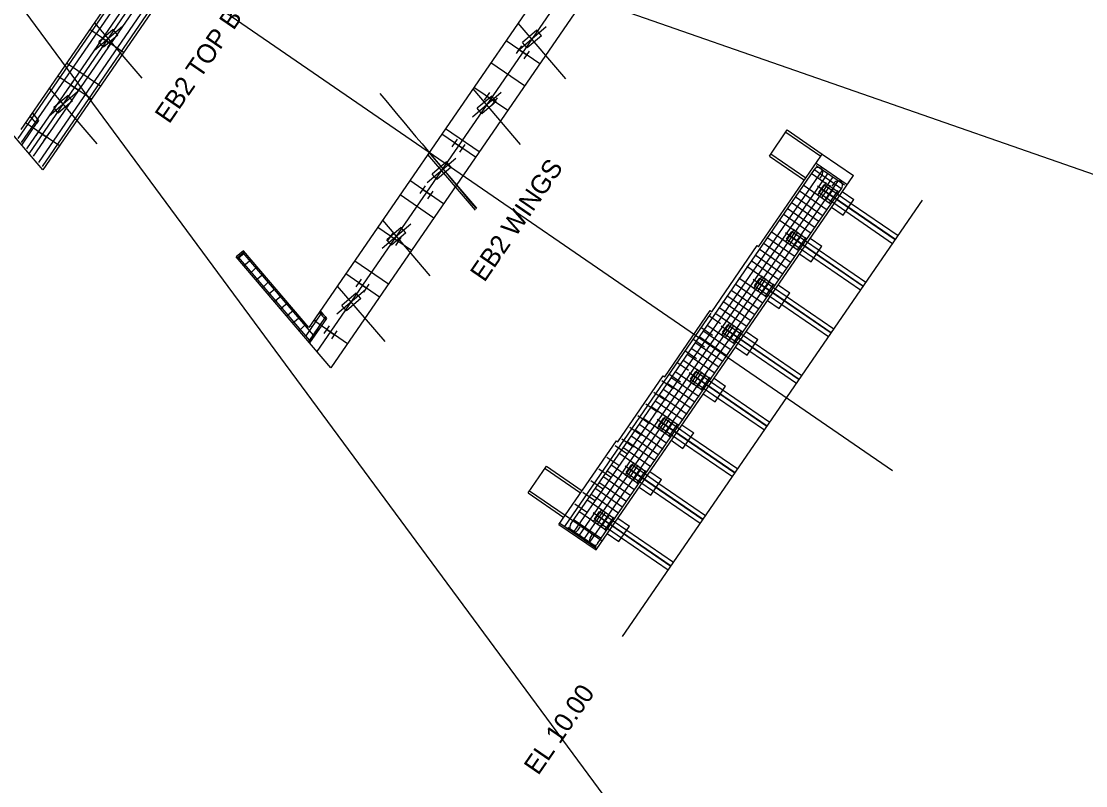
# Model space of a CAD drawing. Extents: x 2378999 to 2381348, y 331302 to 333122.
# Drawn here: x 2379248 to 2379360.9, y 331490.3 to 331571.3 of the extents above; entities that cross this region are included whole.
import ezdxf

# ---------------------------------------------------------------- set-up
doc = ezdxf.new("R2010")
doc.units = 0
for name, color, linetype in [('Arrowhead Terminators', 7, 'Continuous'), ('Dimension Lines', 7, 'Continuous'), ('Dimension Lines CELL', 7, 'Continuous'), ('Mis Work Point CELL', 7, 'Continuous'), ('P_SMU_Bent_Cap', 7, 'Continuous'), ('P_SMU_D_Deck_Outline', 7, 'Continuous'), ('P_SMU_Girder_Concrete', 7, 'Continuous'), ('P_SMU_Mis_L_Lines', 7, 'Continuous'), ('P_SMU_Mis_Long_Chord', 7, 'Continuous'), ('P_SMU_Rebar_B_Bar', 7, 'Continuous'), ('P_SMU_Rebar_H_Bar', 7, 'Continuous'), ('P_SMU_Rebar_K_Bar', 7, 'Continuous'), ('P_SMU_Rebar_U_Bar', 7, 'Continuous'), ('P_SMU_Rebar_V_Bar', 7, 'Continuous'), ('Plan Sheet CELL', 7, 'Continuous'), ('Rebar Lines', 7, 'Continuous'), ('Scratch_Level_0', 7, 'Continuous'), ('Sup Concrete Slab Lines', 7, 'Continuous')]:
    doc.layers.add(name, color=color, linetype=linetype)

msp = doc.modelspace()

# ---------------------------------------------------------------- linework, layer by layer
at = {"layer": 'Arrowhead Terminators'}
for p, q in [((2379247.69, 331558.9), (2379274.11, 331597.35)), ((2379248.06, 331558.46), (2379274.48, 331596.92)), ((2379248.62, 331557.81), (2379275.04, 331596.26)), ((2379275.71, 331595.47), (2379249.3, 331557.02)), ((2379276.27, 331594.82), (2379249.86, 331556.36)), ((2379276.65, 331594.38), (2379250.23, 331555.92)), ((2379306.23, 331517.95), (2379332.11, 331555.6)), ((2379306.57, 331517.12), (2379333, 331555.58)), ((2379307.12, 331516.74), (2379333.55, 331555.2)), ((2379332.91, 331555.05), (2379332.68, 331554.7)), ((2379307.67, 331516.36), (2379334.1, 331554.83)), ((2379308.22, 331515.98), (2379334.65, 331554.45)), ((2379334.18, 331554.17), (2379333.95, 331553.83)), ((2379309.12, 331515.96), (2379334.99, 331553.62)), ((2379305.64, 331517.76), (2379321.16, 331540.36)), ((2379307.04, 331517.39), (2379307.28, 331517.73)), ((2379308.31, 331516.52), (2379308.55, 331516.86))]:
    msp.add_line(p, q, dxfattribs=at)
for centre, start, end in [((2379332.51, 331555.32), 325.5093, 145.5093), ((2379334.59, 331553.9), 325.5093, 145.5093), ((2379306.64, 331517.67), 145.5093, 325.5093), ((2379308.72, 331516.24), 145.5093, 325.5093)]:
    msp.add_arc(centre, 0.49, start, end, dxfattribs=at)
at = {"layer": 'Dimension Lines'}
for p, q in [((2379316.62, 331479.98), (2379154.62, 331699.5)), ((2379368.09, 331552.83), (2379115.15, 331641.03)), ((2379331.75, 331555.23), (2379334.73, 331553.17)), ((2379332.02, 331555.62), (2379335, 331553.57)), ((2379332.29, 331556.01), (2379335.27, 331553.96)), ((2379330.9, 331553.99), (2379333.88, 331551.94)), ((2379332.43, 331552.84), (2379333.37, 331554.21)), ((2379332.84, 331552.55), (2379333.79, 331553.93)), ((2379330.05, 331552.75), (2379333.04, 331550.7)), ((2379330.47, 331553.37), (2379333.46, 331551.32)), ((2379333.25, 331552.27), (2379334.2, 331553.64)), ((2379333.67, 331551.99), (2379334.61, 331553.36)), ((2379329.62, 331552.14), (2379332.61, 331550.08)), ((2379328.77, 331550.9), (2379331.76, 331548.85)), ((2379329.2, 331551.52), (2379332.19, 331549.46)), ((2379328.35, 331550.28), (2379331.34, 331548.23)), ((2379327.07, 331548.43), (2379330.06, 331546.37)), ((2379327.5, 331549.04), (2379330.49, 331546.99)), ((2379329.03, 331547.89), (2379329.98, 331549.26)), ((2379329.44, 331547.61), (2379330.39, 331548.98)), ((2379329.86, 331547.32), (2379330.8, 331548.7)), ((2379330.27, 331547.04), (2379331.21, 331548.41)), ((2379326.23, 331547.19), (2379329.21, 331545.14)), ((2379326.65, 331547.81), (2379329.64, 331545.76)), ((2379325.38, 331545.95), (2379328.36, 331543.9)), ((2379325.8, 331546.57), (2379328.79, 331544.52)), ((2379324.95, 331545.34), (2379327.94, 331543.28)), ((2379324.1, 331544.1), (2379327.09, 331542.05)), ((2379325.63, 331542.94), (2379326.58, 331544.32)), ((2379326.05, 331542.66), (2379326.99, 331544.04)), ((2379326.46, 331542.38), (2379327.4, 331543.75)), ((2379323.25, 331542.86), (2379326.24, 331540.81)), ((2379323.68, 331543.48), (2379326.66, 331541.43)), ((2379326.87, 331542.1), (2379327.81, 331543.47)), ((2379322.4, 331541.63), (2379325.39, 331539.57)), ((2379322.83, 331542.24), (2379325.82, 331540.19)), ((2379321.55, 331540.39), (2379324.54, 331538.34)), ((2379321.98, 331541.01), (2379324.97, 331538.96)), ((2379322.24, 331538), (2379323.18, 331539.37)), ((2379320.28, 331538.54), (2379323.27, 331536.48)), ((2379320.7, 331539.15), (2379323.69, 331537.1)), ((2379322.65, 331537.72), (2379323.59, 331539.09)), ((2379323.06, 331537.43), (2379324, 331538.81)), ((2379323.47, 331537.15), (2379324.42, 331538.52)), ((2379319.43, 331537.3), (2379322.42, 331535.25)), ((2379319.85, 331537.92), (2379322.84, 331535.86)), ((2379318.58, 331536.06), (2379321.57, 331534.01)), ((2379319.01, 331536.68), (2379321.99, 331534.63)), ((2379318.16, 331535.44), (2379321.14, 331533.39)), ((2379316.88, 331533.59), (2379319.87, 331531.54)), ((2379317.31, 331534.21), (2379320.29, 331532.16)), ((2379318.84, 331533.05), (2379319.78, 331534.43)), ((2379319.25, 331532.77), (2379320.19, 331534.14)), ((2379319.66, 331532.49), (2379320.61, 331533.86)), ((2379320.08, 331532.2), (2379321.02, 331533.58)), ((2379316.46, 331532.97), (2379319.44, 331530.92)), ((2379315.61, 331531.74), (2379318.6, 331529.68)), ((2379316.03, 331532.35), (2379319.02, 331530.3)), ((2379314.76, 331530.5), (2379317.75, 331528.45)), ((2379315.18, 331531.12), (2379318.17, 331529.06)), ((2379313.91, 331529.26), (2379316.9, 331527.21)), ((2379315.44, 331528.11), (2379316.38, 331529.48)), ((2379315.85, 331527.83), (2379316.8, 331529.2)), ((2379313.06, 331528.03), (2379316.05, 331525.97)), ((2379313.48, 331528.64), (2379316.47, 331526.59)), ((2379316.27, 331527.54), (2379317.21, 331528.92)), ((2379316.68, 331527.26), (2379317.62, 331528.63)), ((2379312.21, 331526.79), (2379315.2, 331524.74)), ((2379312.63, 331527.41), (2379315.62, 331525.36)), ((2379311.79, 331526.17), (2379314.77, 331524.12)), ((2379311.36, 331525.55), (2379314.35, 331523.5)), ((2379312.04, 331523.16), (2379312.99, 331524.54)), ((2379310.09, 331523.7), (2379313.07, 331521.65)), ((2379310.51, 331524.32), (2379313.5, 331522.26)), ((2379312.46, 331522.88), (2379313.4, 331524.25)), ((2379312.87, 331522.6), (2379313.81, 331523.97)), ((2379313.28, 331522.31), (2379314.22, 331523.69)), ((2379309.24, 331522.46), (2379312.22, 331520.41)), ((2379309.66, 331523.08), (2379312.65, 331521.03)), ((2379308.39, 331521.23), (2379311.38, 331519.17)), ((2379308.81, 331521.85), (2379311.8, 331519.79)), ((2379307.96, 331520.61), (2379310.95, 331518.56)), ((2379307.11, 331519.37), (2379310.1, 331517.32)), ((2379308.65, 331518.22), (2379309.59, 331519.59)), ((2379309.06, 331517.94), (2379310, 331519.31)), ((2379309.47, 331517.65), (2379310.41, 331519.03)), ((2379306.54, 331518.54), (2379309.53, 331516.48)), ((2379309.88, 331517.37), (2379310.83, 331518.74)), ((2379305.97, 331517.7), (2379308.95, 331515.65))]:
    msp.add_line(p, q, dxfattribs=at)
at = {"layer": 'Dimension Lines CELL'}
msp.add_line((2379340.37, 331523.67), (2379157.06, 331649.61), dxfattribs=at)
at = {"layer": 'Mis Work Point CELL'}
for p, q in [((2379248.86, 331557.27), (2379275.48, 331596.01)), ((2379279.4, 331536.29), (2379306.01, 331575.03)), ((2379311.76, 331506.1), (2379343.54, 331552.36))]:
    msp.add_line(p, q, dxfattribs=at)
at = {"layer": 'P_SMU_Bent_Cap'}
for p, q in [((2379258.78, 331570.79), (2379255.74, 331568.19)), ((2379303.68, 331570.72), (2379300.64, 331568.12)), ((2379253.99, 331563.82), (2379250.95, 331561.23)), ((2379298.89, 331563.75), (2379295.85, 331561.15)), ((2379294.1, 331556.78), (2379291.06, 331554.18)), ((2379289.31, 331549.81), (2379286.27, 331547.22)), ((2379284.53, 331542.85), (2379281.48, 331540.25))]:
    msp.add_line(p, q, dxfattribs=at)
at = {"layer": 'P_SMU_D_Deck_Outline'}
for p, q in [((2379257.78, 331570.43), (2379256.25, 331569.13)), ((2379258.26, 331569.86), (2379256.74, 331568.56)), ((2379258.26, 331569.86), (2379257.78, 331570.43)), ((2379302.67, 331570.36), (2379301.15, 331569.06)), ((2379303.16, 331569.79), (2379301.64, 331568.49)), ((2379303.16, 331569.79), (2379302.67, 331570.36)), ((2379256.74, 331568.56), (2379256.25, 331569.13)), ((2379301.64, 331568.49), (2379301.15, 331569.06)), ((2379252.99, 331563.46), (2379251.47, 331562.16)), ((2379253.47, 331562.89), (2379251.95, 331561.59)), ((2379253.47, 331562.89), (2379252.99, 331563.46)), ((2379297.89, 331563.39), (2379296.36, 331562.09)), ((2379298.37, 331562.82), (2379297.89, 331563.39)), ((2379251.95, 331561.59), (2379251.47, 331562.16)), ((2379296.85, 331561.52), (2379296.36, 331562.09)), ((2379298.37, 331562.82), (2379296.85, 331561.52)), ((2379293.1, 331556.42), (2379291.58, 331555.12)), ((2379293.58, 331555.85), (2379293.1, 331556.42)), ((2379292.06, 331554.55), (2379291.58, 331555.12)), ((2379293.58, 331555.85), (2379292.06, 331554.55)), ((2379288.31, 331549.45), (2379286.79, 331548.15)), ((2379288.8, 331548.88), (2379288.31, 331549.45)), ((2379288.8, 331548.88), (2379287.28, 331547.58)), ((2379287.28, 331547.58), (2379286.79, 331548.15)), ((2379283.52, 331542.48), (2379282, 331541.18)), ((2379284.01, 331541.91), (2379282.49, 331540.61)), ((2379284.01, 331541.91), (2379283.52, 331542.48)), ((2379282.49, 331540.61), (2379282, 331541.18))]:
    msp.add_line(p, q, dxfattribs=at)
at = {"layer": 'P_SMU_Girder_Concrete'}
for p, q in [((2379256.38, 331569.09), (2379256.95, 331569.91)), ((2379256.67, 331569.5), (2379257.48, 331568.94)), ((2379257.19, 331568.53), (2379257.76, 331569.36)), ((2379300.51, 331567.89), (2379301.08, 331568.72)), ((2379300.79, 331568.3), (2379301.6, 331567.75)), ((2379301.32, 331567.33), (2379301.89, 331568.16)), ((2379252.99, 331564.14), (2379253.55, 331564.97)), ((2379253.27, 331564.56), (2379254.08, 331564)), ((2379253.8, 331563.59), (2379254.36, 331564.41)), ((2379297.11, 331562.95), (2379297.68, 331563.77)), ((2379297.39, 331563.36), (2379298.2, 331562.8)), ((2379297.92, 331562.39), (2379298.49, 331563.21)), ((2379249.59, 331559.2), (2379250.15, 331560.02)), ((2379249.87, 331559.61), (2379250.68, 331559.05)), ((2379250.4, 331558.64), (2379250.97, 331559.47)), ((2379293.71, 331558), (2379294.28, 331558.82)), ((2379294, 331558.41), (2379294.81, 331557.86)), ((2379294.52, 331557.44), (2379295.09, 331558.27)), ((2379290.32, 331553.06), (2379290.88, 331553.88)), ((2379332.55, 331553.16), (2379333.12, 331553.98)), ((2379333.12, 331553.98), (2379336, 331552)), ((2379290.6, 331553.47), (2379291.41, 331552.91)), ((2379291.13, 331552.5), (2379291.69, 331553.32)), ((2379332.55, 331553.16), (2379335.43, 331551.18)), ((2379332.82, 331553.55), (2379340.66, 331548.17)), ((2379332.84, 331553.58), (2379340.68, 331548.2)), ((2379336, 331552), (2379340.96, 331548.6)), ((2379335.43, 331551.18), (2379340.39, 331547.77)), ((2379286.92, 331548.11), (2379287.48, 331548.93)), ((2379287.2, 331548.52), (2379288.01, 331547.97)), ((2379287.73, 331547.55), (2379288.3, 331548.38)), ((2379329.15, 331548.21), (2379329.72, 331549.04)), ((2379329.15, 331548.21), (2379332.04, 331546.23)), ((2379329.42, 331548.61), (2379337.26, 331543.22)), ((2379329.45, 331548.64), (2379337.29, 331543.25)), ((2379329.72, 331549.04), (2379332.6, 331547.05)), ((2379332.04, 331546.23), (2379336.99, 331542.83)), ((2379332.6, 331547.05), (2379337.56, 331543.65)), ((2379283.52, 331543.16), (2379284.09, 331543.99)), ((2379325.75, 331543.27), (2379326.32, 331544.09)), ((2379326.05, 331543.69), (2379333.89, 331538.31)), ((2379326.32, 331544.09), (2379329.21, 331542.11)), ((2379283.8, 331543.58), (2379284.61, 331543.02)), ((2379284.33, 331542.61), (2379284.9, 331543.43)), ((2379325.75, 331543.27), (2379328.64, 331541.28)), ((2379326.03, 331543.66), (2379333.87, 331538.28)), ((2379329.21, 331542.11), (2379334.16, 331538.7)), ((2379328.64, 331541.28), (2379333.59, 331537.88)), ((2379280.12, 331538.22), (2379280.69, 331539.04)), ((2379280.41, 331538.63), (2379281.22, 331538.07)), ((2379280.93, 331537.66), (2379281.5, 331538.49)), ((2379322.36, 331538.32), (2379322.92, 331539.15)), ((2379322.36, 331538.32), (2379325.24, 331536.34)), ((2379322.63, 331538.72), (2379330.47, 331533.33)), ((2379322.65, 331538.75), (2379330.49, 331533.36)), ((2379322.92, 331539.15), (2379325.81, 331537.16)), ((2379325.81, 331537.16), (2379330.76, 331533.76)), ((2379325.24, 331536.34), (2379330.2, 331532.94)), ((2379318.96, 331533.38), (2379319.53, 331534.2)), ((2379319.23, 331533.77), (2379327.07, 331528.39)), ((2379319.25, 331533.8), (2379327.09, 331528.42)), ((2379319.53, 331534.2), (2379322.41, 331532.22)), ((2379318.96, 331533.38), (2379321.84, 331531.39)), ((2379321.84, 331531.39), (2379326.8, 331527.99)), ((2379322.41, 331532.22), (2379327.37, 331528.81)), ((2379315.56, 331528.43), (2379316.13, 331529.26)), ((2379316.13, 331529.26), (2379319.01, 331527.27)), ((2379315.56, 331528.43), (2379318.45, 331526.45)), ((2379315.83, 331528.83), (2379323.67, 331523.44)), ((2379315.85, 331528.86), (2379323.69, 331523.47)), ((2379319.01, 331527.27), (2379323.97, 331523.87)), ((2379318.45, 331526.45), (2379323.4, 331523.04)), ((2379312.16, 331523.49), (2379312.73, 331524.31)), ((2379312.16, 331523.49), (2379315.05, 331521.5)), ((2379312.44, 331523.88), (2379320.28, 331518.5)), ((2379312.46, 331523.91), (2379320.3, 331518.53)), ((2379312.73, 331524.31), (2379315.61, 331522.33)), ((2379315.61, 331522.33), (2379320.57, 331518.92)), ((2379315.05, 331521.5), (2379320, 331518.1)), ((2379308.77, 331518.54), (2379309.33, 331519.36)), ((2379309.04, 331518.94), (2379316.88, 331513.55)), ((2379309.06, 331518.97), (2379316.9, 331513.58)), ((2379309.33, 331519.36), (2379312.22, 331517.38)), ((2379308.77, 331518.54), (2379311.65, 331516.56)), ((2379312.22, 331517.38), (2379317.17, 331513.98)), ((2379311.65, 331516.56), (2379316.61, 331513.15))]:
    msp.add_line(p, q, dxfattribs=at)
at = {"layer": 'P_SMU_Mis_L_Lines'}
for p, q in [((2379260.85, 331565.29), (2379255.8, 331571.2)), ((2379305.74, 331565.22), (2379300.7, 331571.13)), ((2379256.06, 331558.33), (2379251.01, 331564.23)), ((2379300.96, 331558.25), (2379295.91, 331564.16)), ((2379296.17, 331551.28), (2379291.12, 331557.19)), ((2379291.38, 331544.32), (2379286.34, 331550.22)), ((2379286.59, 331537.35), (2379281.55, 331543.25))]:
    msp.add_line(p, q, dxfattribs=at)
at = {"layer": 'P_SMU_Mis_Long_Chord'}
msp.add_arc((2384724.21, 336097.17), 7080, 219.816017, 219.945167, dxfattribs=at)
at = {"layer": 'P_SMU_Rebar_B_Bar'}
for p, q in [((2379273.43, 331596.86), (2379247.99, 331559.83)), ((2379276.93, 331594.3), (2379250.32, 331555.57)), ((2379303.97, 331575.88), (2379278.52, 331538.85)), ((2379307.47, 331573.33), (2379280.85, 331534.59)), ((2379250.32, 331555.57), (2379240.28, 331567.31)), ((2379256.41, 331564.43), (2379252.83, 331566.88)), ((2379301.38, 331564.46), (2379297.81, 331566.92)), ((2379248.08, 331558.19), (2379249.86, 331560.79)), ((2379296.57, 331557.46), (2379293, 331559.91)), ((2379327.32, 331557.02), (2379329.22, 331559.79)), ((2379329.07, 331559.57), (2379332.78, 331557.02)), ((2379329.22, 331559.79), (2379332.93, 331557.24)), ((2379327.48, 331557.25), (2379331.19, 331554.71)), ((2379332.78, 331557.02), (2379332.93, 331557.24)), ((2379332.93, 331557.24), (2379336.23, 331554.98)), ((2379326.18, 331547.42), (2379332.78, 331557.02)), ((2379327.32, 331557.02), (2379331.03, 331554.47)), ((2379332.27, 331556.28), (2379335.57, 331554.02)), ((2379308.95, 331515.28), (2379336.23, 331554.98)), ((2379291.75, 331550.45), (2379288.18, 331552.91)), ((2379335.05, 331553.26), (2379336.28, 331552.41)), ((2379333.91, 331551.61), (2379335.15, 331550.76)), ((2379335.15, 331550.76), (2379336.28, 331552.41)), ((2379331.65, 331548.32), (2379332.89, 331547.47)), ((2379321.21, 331540.53), (2379326.02, 331547.53)), ((2379326.02, 331547.53), (2379326.18, 331547.42)), ((2379331.75, 331545.82), (2379332.89, 331547.47)), ((2379271.58, 331546.98), (2379270.82, 331546.33)), ((2379280.85, 331534.59), (2379270.82, 331546.33)), ((2379278.52, 331538.85), (2379271.58, 331546.98)), ((2379330.52, 331546.67), (2379331.75, 331545.82)), ((2379286.94, 331543.45), (2379283.37, 331545.9)), ((2379328.25, 331543.37), (2379329.49, 331542.52)), ((2379327.12, 331541.72), (2379328.36, 331540.87)), ((2379328.36, 331540.87), (2379329.49, 331542.52)), ((2379316.24, 331533.63), (2379321.05, 331540.64)), ((2379321.05, 331540.64), (2379321.21, 331540.53)), ((2379278.61, 331537.21), (2379280.4, 331539.81)), ((2379324.85, 331538.43), (2379326.09, 331537.58)), ((2379324.96, 331535.93), (2379326.09, 331537.58)), ((2379323.72, 331536.78), (2379324.96, 331535.93)), ((2379311.27, 331526.73), (2379316.08, 331533.74)), ((2379316.08, 331533.74), (2379316.24, 331533.63)), ((2379321.46, 331533.48), (2379322.69, 331532.63)), ((2379321.56, 331530.98), (2379322.69, 331532.63)), ((2379320.32, 331531.83), (2379321.56, 331530.98)), ((2379318.06, 331528.53), (2379319.3, 331527.69)), ((2379305.02, 331517.98), (2379311.11, 331526.84)), ((2379311.11, 331526.84), (2379311.27, 331526.73)), ((2379316.93, 331526.89), (2379318.16, 331526.04)), ((2379318.16, 331526.04), (2379319.3, 331527.69)), ((2379301.76, 331521.31), (2379303.7, 331524.14)), ((2379303.55, 331523.91), (2379307.31, 331521.32)), ((2379303.7, 331524.14), (2379307.47, 331521.55)), ((2379314.66, 331523.59), (2379315.9, 331522.74)), ((2379314.77, 331521.09), (2379315.9, 331522.74)), ((2379301.76, 331521.31), (2379305.53, 331518.72)), ((2379301.91, 331521.53), (2379305.68, 331518.94)), ((2379313.53, 331521.94), (2379314.77, 331521.09)), ((2379305.68, 331518.94), (2379309.61, 331516.24)), ((2379305.02, 331517.98), (2379308.95, 331515.28)), ((2379311.26, 331518.64), (2379312.5, 331517.79)), ((2379311.37, 331516.15), (2379312.5, 331517.79)), ((2379310.13, 331517), (2379311.37, 331516.15))]:
    msp.add_line(p, q, dxfattribs=at)
msp.add_lwpolyline([(2379249.2, 331561.59), (2379249.86, 331560.79), (2379249.64, 331560.47), (2379248.98, 331561.27)], close=True, dxfattribs=at)
for centre in [(2384693.68, 336118.15), (2384724.21, 336097.17)]:
    msp.add_arc(centre, 7099.63, 219.926438, 219.934816, dxfattribs=at)
at = {"layer": 'P_SMU_Rebar_H_Bar'}
for p, q in [((2379278.6, 331537.48), (2379271.05, 331546.32)), ((2379278.99, 331538.05), (2379271.56, 331546.75)), ((2379279.07, 331538.17), (2379278.6, 331537.48)), ((2379279.46, 331538.74), (2379278.99, 331538.05))]:
    msp.add_line(p, q, dxfattribs=at)
at = {"layer": 'P_SMU_Rebar_K_Bar'}
for p, q in [((2379279.77, 331540.3), (2379278.18, 331537.98)), ((2379280.16, 331539.84), (2379278.57, 331537.52))]:
    msp.add_line(p, q, dxfattribs=at)
at = {"layer": 'P_SMU_Rebar_U_Bar'}
for p, q in [((2379320.91, 331540.13), (2379322.14, 331539.28)), ((2379320.06, 331538.89), (2379321.29, 331538.04)), ((2379319.21, 331537.66), (2379320.44, 331536.81)), ((2379318.36, 331536.42), (2379319.6, 331535.57)), ((2379317.51, 331535.18), (2379318.75, 331534.33)), ((2379316.66, 331533.95), (2379317.9, 331533.1)), ((2379315.93, 331533.23), (2379317.17, 331532.38)), ((2379315.08, 331532), (2379316.32, 331531.15)), ((2379314.23, 331530.76), (2379315.47, 331529.91)), ((2379313.38, 331529.53), (2379314.62, 331528.68)), ((2379312.54, 331528.29), (2379313.77, 331527.44)), ((2379311.69, 331527.05), (2379312.92, 331526.2)), ((2379310.96, 331526.34), (2379312.2, 331525.49)), ((2379310.11, 331525.1), (2379311.35, 331524.25)), ((2379309.26, 331523.87), (2379310.5, 331523.02)), ((2379308.41, 331522.63), (2379309.65, 331521.78)), ((2379307.56, 331521.39), (2379308.8, 331520.54)), ((2379306.71, 331520.16), (2379307.95, 331519.31))]:
    msp.add_line(p, q, dxfattribs=at)
at = {"layer": 'P_SMU_Rebar_V_Bar'}
for centre in [(2379271.12, 331546.27), (2379271.6, 331546.67), (2379271.77, 331545.51), (2379272.25, 331545.91), (2379272.9, 331545.15), (2379272.42, 331544.75), (2379273.07, 331543.99), (2379273.55, 331544.39), (2379273.72, 331543.22), (2379274.19, 331543.63), (2379274.84, 331542.87), (2379274.37, 331542.46), (2379275.02, 331541.7), (2379275.49, 331542.11), (2379275.67, 331540.94), (2379276.14, 331541.35), (2379276.79, 331540.59), (2379279.75, 331540.3), (2379276.32, 331540.18), (2379276.97, 331539.42), (2379277.44, 331539.83), (2379279.28, 331539.61), (2379280.16, 331539.8), (2379277.62, 331538.66), (2379278.09, 331539.07), (2379278.54, 331538.54), (2379278.8, 331538.93), (2379278.96, 331538.05), (2379279.22, 331538.43), (2379279.69, 331539.12), (2379278.17, 331538.01), (2379278.6, 331537.52)]:
    msp.add_circle(centre, 0.0208, dxfattribs=at)
at = {"layer": 'Plan Sheet CELL'}
msp.add_line((2379296.31, 331551.5), (2379291.27, 331557.4), dxfattribs=at)
at = {"layer": 'Rebar Lines'}
for p, q in [((2379258.86, 331568), (2379255.29, 331570.45)), ((2379302.98, 331566.8), (2379299.41, 331569.25)), ((2379255.46, 331563.05), (2379251.89, 331565.5)), ((2379299.59, 331561.85), (2379296.01, 331564.31)), ((2379252.06, 331558.1), (2379248.49, 331560.56)), ((2379296.19, 331556.91), (2379292.62, 331559.36)), ((2379292.79, 331551.96), (2379289.22, 331554.42)), ((2379332.41, 331553.86), (2379340.67, 331548.18)), ((2379289.39, 331547.02), (2379285.82, 331549.47)), ((2379329.02, 331548.91), (2379337.27, 331543.24)), ((2379285.99, 331542.07), (2379282.42, 331544.53)), ((2379325.62, 331543.97), (2379333.88, 331538.29)), ((2379282.6, 331537.13), (2379279.03, 331539.58)), ((2379322.22, 331539.02), (2379330.48, 331533.35)), ((2379318.82, 331534.08), (2379327.08, 331528.4)), ((2379315.43, 331529.13), (2379323.68, 331523.46)), ((2379312.03, 331524.19), (2379320.29, 331518.51)), ((2379308.63, 331519.24), (2379316.89, 331513.57))]:
    msp.add_line(p, q, dxfattribs=at)
at = {"layer": 'Scratch_Level_0'}
for p, q in [((2379271.68, 331546.86), (2379270.92, 331546.21)), ((2379271.74, 331546.79), (2379270.98, 331546.14)), ((2379272.39, 331546.03), (2379271.63, 331545.38)), ((2379273.04, 331545.27), (2379272.28, 331544.62)), ((2379273.69, 331544.51), (2379272.93, 331543.86)), ((2379274.34, 331543.75), (2379273.58, 331543.1)), ((2379274.99, 331542.99), (2379274.23, 331542.34)), ((2379275.64, 331542.23), (2379274.88, 331541.58)), ((2379276.29, 331541.47), (2379275.53, 331540.82)), ((2379276.94, 331540.71), (2379276.18, 331540.06)), ((2379277.59, 331539.95), (2379276.82, 331539.3)), ((2379278.23, 331539.19), (2379277.47, 331538.54)), ((2379278.47, 331537.3), (2379280.29, 331539.95)), ((2379305.12, 331518.12), (2379309.05, 331515.42))]:
    msp.add_line(p, q, dxfattribs=at)
msp.add_arc((2384724.21, 336097.17), 7099.79, 219.926438, 219.934816, dxfattribs=at)

# ---------------------------------------------------------------- texts
at = {"layer": 'Sup Concrete Slab Lines'}
for s, p in [('EB2 TOP B BARS', (2379263.7, 331560.36)), ('EB2 WINGS', (2379297.12, 331543.57)), ('EL 10.00', (2379302.82, 331491.29))]:
    msp.add_text(s, height=2, rotation=55.5093, dxfattribs=at).set_placement(p)

doc.saveas('drawing.dxf')
